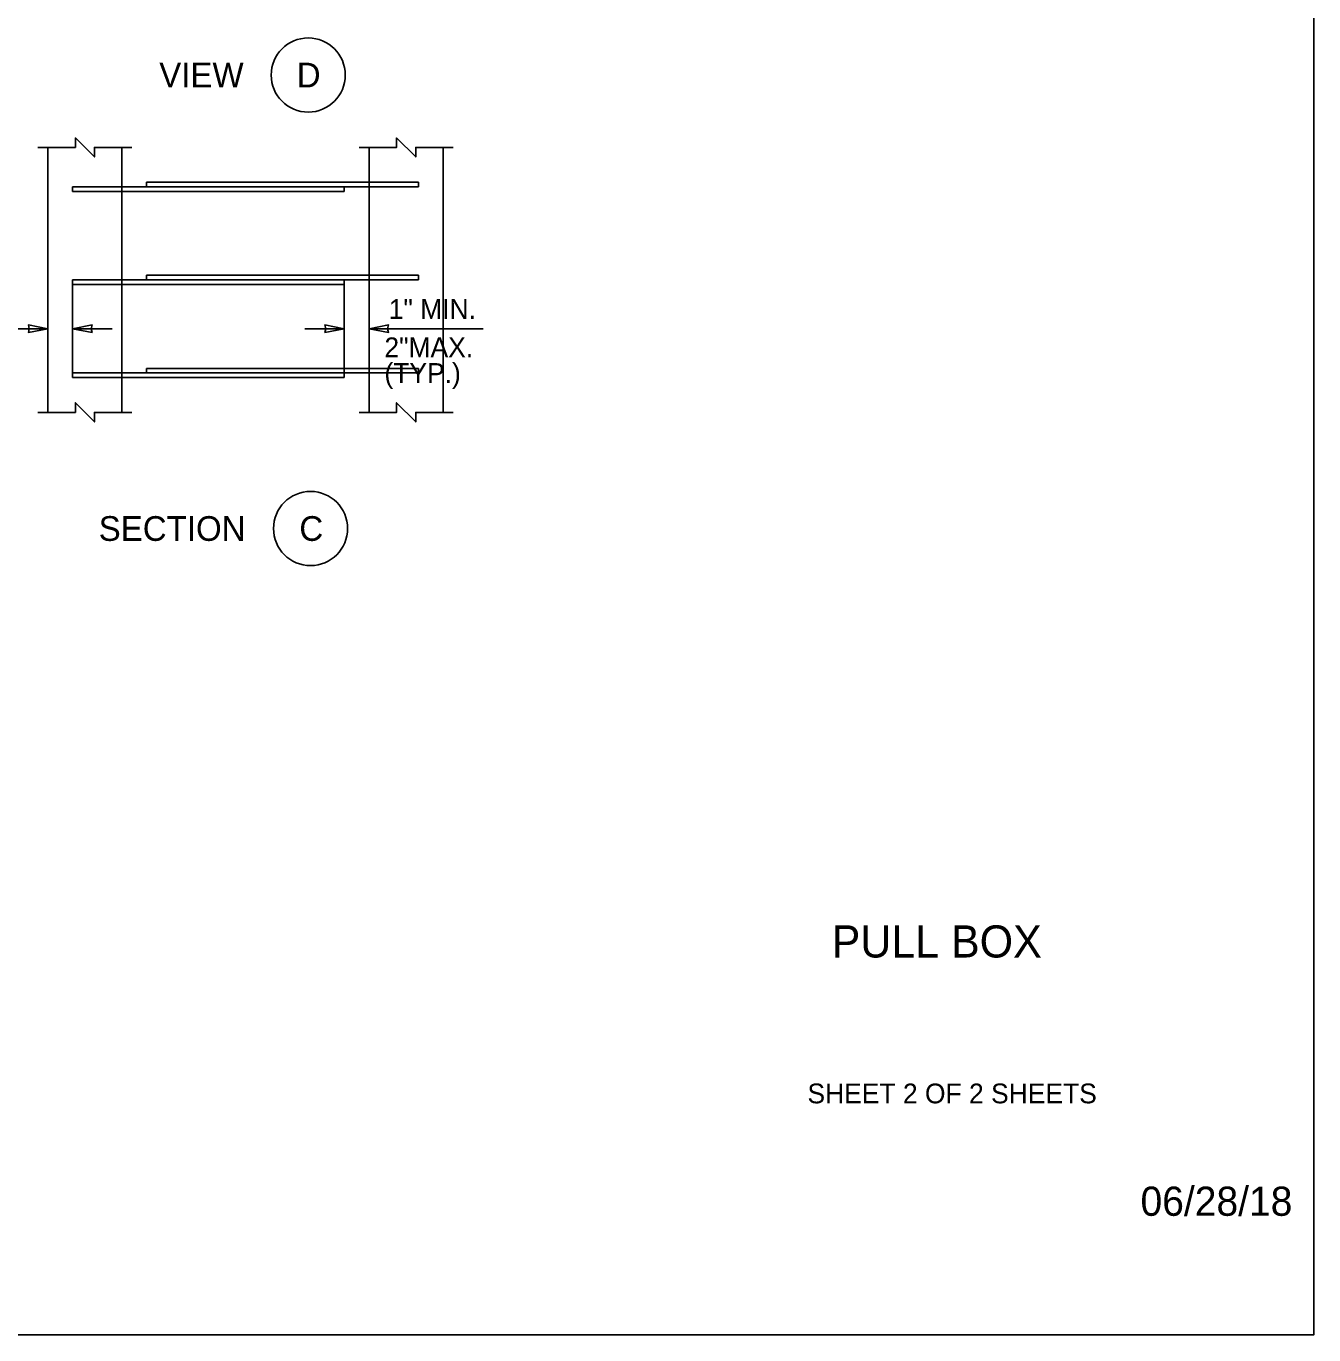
# Model space of a CAD drawing. Extents: x 99862 to 103151, y 100000 to 105076.
# Drawn here: x 102109 to 103151, y 103000 to 104058 of the extents above; entities that cross this region are included whole.
import ezdxf

# ---------------------------------------------------------------- set-up
doc = ezdxf.new("R2010")
doc.units = 0
for name, color, linetype in [('Level 1', 7, 'Continuous'), ('Level 14', 7, 'Continuous'), ('Level 15', 7, 'Continuous'), ('Level 2', 7, 'Continuous'), ('Level 20', 7, 'Continuous'), ('Level 62', 7, 'Continuous')]:
    doc.layers.add(name, color=color, linetype=linetype)

msp = doc.modelspace()

# ---------------------------------------------------------------- linework, layer by layer
at = {"layer": 'Level 1'}
msp.add_lwpolyline([(99862, 102999.5), (103151, 102999.5), (103151, 105075.5), (99862, 105075.5)], close=True, dxfattribs=at)
at = {"layer": 'Level 14'}
for p, q in [((102186.2, 103928.4), (102146.2, 103928.4)), ((102146.2, 103928.4), (102146.2, 103924.6)), ((102186.2, 103928.4), (102366.2, 103928.4)), ((102386.2, 103932.1), (102206.2, 103932.1)), ((102206.2, 103928.4), (102206.2, 103932.1)), ((102206.2, 103928.4), (102386.2, 103928.4)), ((102366.2, 103924.6), (102366.2, 103928.4)), ((102386.2, 103932.1), (102426.2, 103932.1)), ((102426.2, 103928.4), (102386.2, 103928.4)), ((102426.2, 103932.1), (102426.2, 103928.4)), ((102146.2, 103924.6), (102186.2, 103924.6)), ((102366.2, 103924.6), (102186.2, 103924.6)), ((102186.2, 103853.1), (102146.2, 103853.1)), ((102146.2, 103853.1), (102146.2, 103849.3)), ((102186.2, 103853.1), (102366.2, 103853.1)), ((102386.2, 103856.8), (102206.2, 103856.8)), ((102206.2, 103853.1), (102206.2, 103856.8)), ((102206.2, 103853.1), (102386.2, 103853.1)), ((102366.2, 103849.3), (102366.2, 103853.1)), ((102386.2, 103856.8), (102426.2, 103856.8)), ((102426.2, 103853.1), (102386.2, 103853.1)), ((102426.2, 103856.8), (102426.2, 103853.1)), ((102146.2, 103849.3), (102186.2, 103849.3)), ((102366.2, 103849.3), (102186.2, 103849.3)), ((102386.2, 103781.5), (102206.2, 103781.5)), ((102206.2, 103777.8), (102206.2, 103781.5)), ((102386.2, 103781.5), (102426.2, 103781.5)), ((102426.2, 103781.5), (102426.2, 103777.8)), ((102186.2, 103777.8), (102146.2, 103777.8)), ((102146.2, 103777.8), (102146.2, 103774)), ((102146.2, 103774), (102186.2, 103774)), ((102186.2, 103777.8), (102366.2, 103777.8)), ((102366.2, 103774), (102186.2, 103774)), ((102206.2, 103777.8), (102386.2, 103777.8)), ((102366.2, 103774), (102366.2, 103777.8)), ((102426.2, 103777.8), (102386.2, 103777.8))]:
    msp.add_line(p, q, dxfattribs=at)
at = {"layer": 'Level 15'}
for p, q in [((102146.2, 103849.3), (102146.2, 103777.8)), ((102366.2, 103849.3), (102366.2, 103777.8)), ((101941.4, 103813.5), (102126.2, 103813.5)), ((102146.2, 103813.5), (102178.2, 103813.5)), ((102334.2, 103813.5), (102366.2, 103813.5)), ((102386.2, 103813.5), (102478.7, 103813.5))]:
    msp.add_line(p, q, dxfattribs=at)
for points in [[(102118.2, 103960.2), (102148.5, 103960.2), (102148.5, 103968), (102164, 103952.5), (102164, 103960.2), (102194.2, 103960.2)], [(102378.2, 103960.2), (102408.5, 103960.2), (102408.5, 103968), (102424, 103952.5), (102424, 103960.2), (102454.2, 103960.2)], [(102118.2, 103745.9), (102148.5, 103745.9), (102148.5, 103753.6), (102164, 103738.2), (102164, 103745.9), (102194.2, 103745.9)], [(102378.2, 103745.9), (102408.5, 103745.9), (102408.5, 103753.6), (102424, 103738.2), (102424, 103745.9), (102454.2, 103745.9)]]:
    msp.add_lwpolyline(points, dxfattribs=at)
for points in [[(102126.2, 103813.5), (102110.5, 103810.5), (102111.2, 103813.5), (102110.5, 103816.6)], [(102146.2, 103813.5), (102162, 103810.5), (102161.2, 103813.5), (102162, 103816.6)], [(102366.2, 103813.5), (102350.5, 103810.5), (102351.2, 103813.5), (102350.5, 103816.6)], [(102386.2, 103813.5), (102402, 103810.5), (102401.2, 103813.5), (102402, 103816.6)]]:
    msp.add_lwpolyline(points, close=True, dxfattribs=at)
at = {"layer": 'Level 2'}
for p, q in [((102126.2, 103960.2), (102126.2, 103745.9)), ((102186.2, 103960.2), (102186.2, 103745.9)), ((102386.2, 103960.2), (102386.2, 103745.9)), ((102446.2, 103960.2), (102446.2, 103745.9))]:
    msp.add_line(p, q, dxfattribs=at)
at = {"layer": 'Level 20'}
for centre in [(102337, 104018.8), (102338.9, 103651.9)]:
    msp.add_circle(centre, 30, dxfattribs=at)

# ---------------------------------------------------------------- texts
at = {"layer": 'Level 15'}
msp.add_text('06/28/18', height=23.62, dxfattribs=at).set_placement((103010.7, 103095.8))
at = {"layer": 'Level 20'}
for s, height, p in [('VIEW', 20, (102216.4, 104008.9)), ('D', 20, (102327.7, 104008.8)), ('1" MIN.', 16, (102402.2, 103821.5)), ('2"MAX.', 16, (102398.7, 103790.5)), ('(TYP.)', 16, (102398.7, 103769.7)), ('SECTION', 20, (102167.4, 103641.9)), ('C', 20, (102329.8, 103641.9))]:
    msp.add_text(s, height=height, dxfattribs=at).set_placement(p)
at = {"layer": 'Level 62'}
for s, height, p in [('PULL BOX', 26, (102760.7, 103304.8)), ('SHEET 2 OF 2 SHEETS', 16, (102741.1, 103186.8))]:
    msp.add_text(s, height=height, dxfattribs=at).set_placement(p)

doc.saveas('drawing.dxf')
